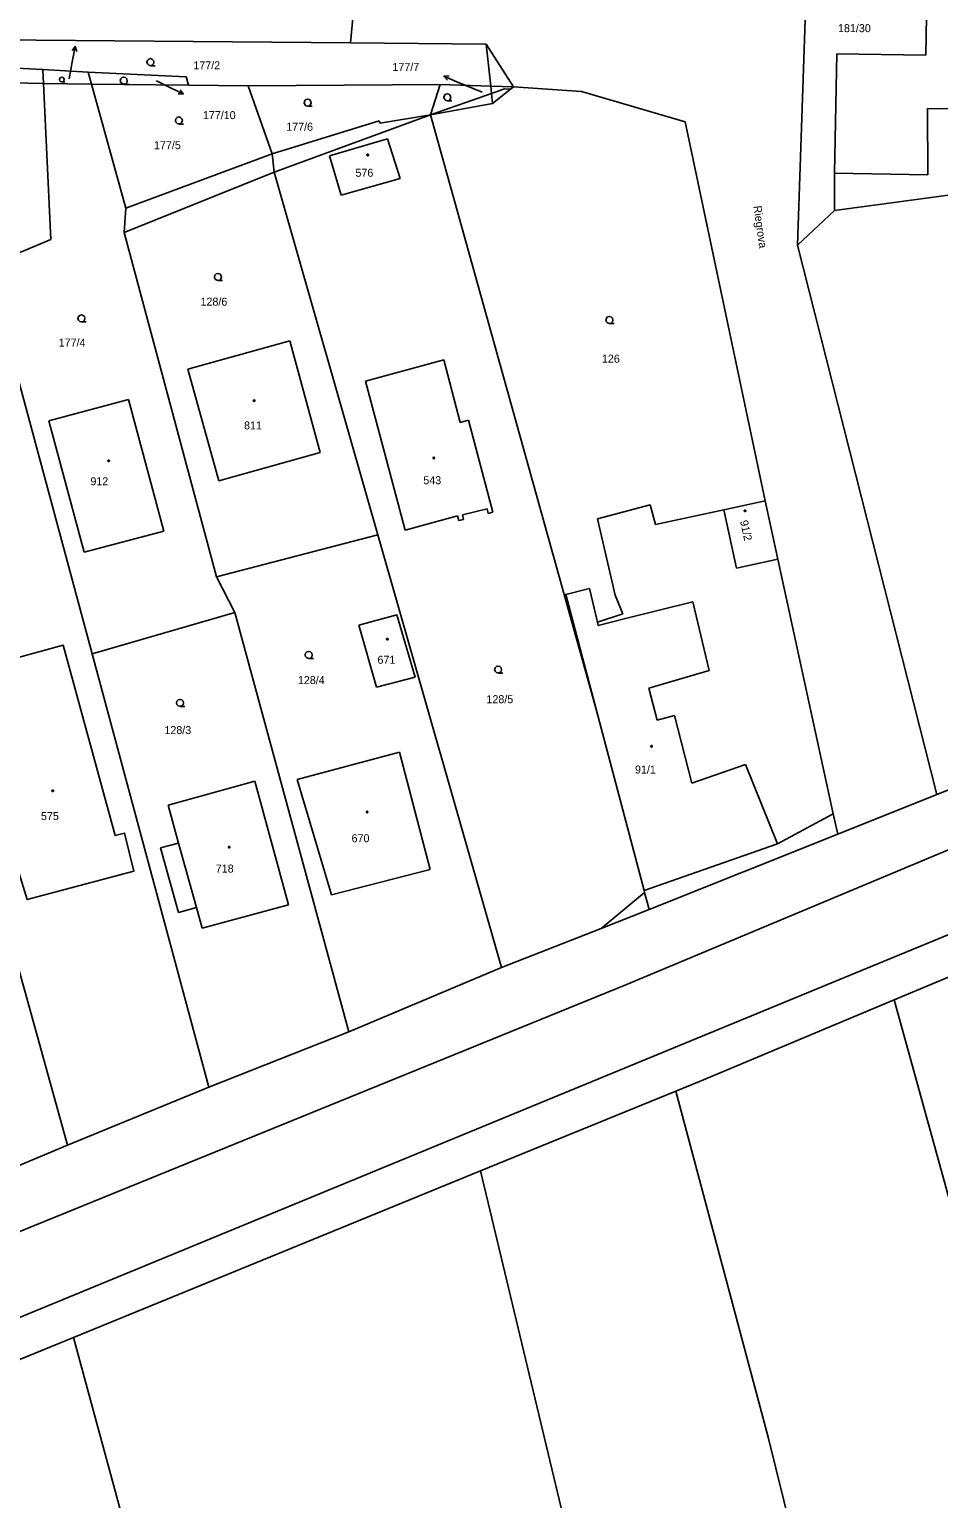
# Model space of a CAD drawing. Extents: x -757994 to -755874, y -1047691 to -1046119.
# Drawn here: x -756280.1 to -756183.5, y -1046741.5 to -1046585.4 of the extents above; entities that cross this region are included whole.
import ezdxf

# ---------------------------------------------------------------- set-up
doc = ezdxf.new("R2010")
doc.units = 0
doc.layers.add('katastrální mapa', color=7, linetype='Continuous')

msp = doc.modelspace()

# ---------------------------------------------------------------- linework, layer by layer
at = {"layer": 'katastrální mapa'}
for p, q in [((-756184.77, -1046581.39), (-756184.91, -1046588.16)), ((-756245.59, -1046582.7), (-756246, -1046586.87)), ((-756197.7, -1046584.41), (-756198.54, -1046608.36)), ((-756246, -1046586.87), (-756293.36, -1046586.44)), ((-756231.57, -1046587), (-756246, -1046586.87)), ((-756275.21, -1046587.24), (-756275.49, -1046588.71)), ((-756228.67, -1046591.53), (-756231.57, -1046587)), ((-756231.1, -1046591.45), (-756231.57, -1046587)), ((-756194.33, -1046588.02), (-756194.61, -1046600.7)), ((-756184.91, -1046588.16), (-756194.33, -1046588.02)), ((-756292.75, -1046588.97), (-756278.67, -1046589.7)), ((-756278.6, -1046591.16), (-756278.67, -1046589.7)), ((-756278.67, -1046589.7), (-756273.85, -1046589.96)), ((-756275.87, -1046590.68), (-756275.49, -1046588.71)), ((-756273.85, -1046589.96), (-756273.49, -1046591.25)), ((-756278.6, -1046591.16), (-756292.3, -1046590.87)), ((-756277.82, -1046607.75), (-756278.6, -1046591.16)), ((-756278.6, -1046591.16), (-756273.49, -1046591.25)), ((-756273.49, -1046591.25), (-756269.84, -1046604.41)), ((-756273.49, -1046591.25), (-756263.18, -1046591.35)), ((-756266.57, -1046590.9), (-756265.09, -1046591.62)), ((-756263.18, -1046591.35), (-756256.84, -1046591.41)), ((-756256.84, -1046591.41), (-756236.47, -1046591.28)), ((-756256.84, -1046591.41), (-756254.32, -1046598.66)), ((-756236.47, -1046591.28), (-756237.5, -1046594.5)), ((-756236.47, -1046591.28), (-756231.1, -1046591.45)), ((-756236.07, -1046590.41), (-756234.68, -1046590.98)), ((-756232.01, -1046592.08), (-756234.68, -1046590.98)), ((-756231.1, -1046591.45), (-756228.67, -1046591.53)), ((-756231.01, -1046592.22), (-756231.1, -1046591.45)), ((-756228.67, -1046591.53), (-756228.98, -1046591.78)), ((-756221.46, -1046592.04), (-756228.67, -1046591.53)), ((-756263.74, -1046592.28), (-756265.09, -1046591.62)), ((-756237.5, -1046594.5), (-756231.01, -1046592.22)), ((-756231.01, -1046592.22), (-756229.64, -1046591.74)), ((-756230.9, -1046593.3), (-756231.01, -1046592.22)), ((-756228.98, -1046591.78), (-756230.9, -1046593.3)), ((-756229.64, -1046591.74), (-756228.98, -1046591.78)), ((-756210.44, -1046595.24), (-756221.46, -1046592.04)), ((-756237.5, -1046594.5), (-756254.1, -1046600.6)), ((-756242.84, -1046595.37), (-756237.5, -1046594.5)), ((-756230.9, -1046593.3), (-756237.5, -1046594.5)), ((-756237.5, -1046594.5), (-756223.29, -1046645.47)), ((-756184.67, -1046600.87), (-756184.71, -1046593.82)), ((-756184.71, -1046593.82), (-756154.21, -1046594.17)), ((-756254.32, -1046598.66), (-756242.94, -1046595.13)), ((-756242.94, -1046595.13), (-756242.84, -1046595.37)), ((-756201.96, -1046635.51), (-756210.44, -1046595.24)), ((-756248.2, -1046598.87), (-756242.04, -1046597.06)), ((-756242.04, -1046597.06), (-756240.72, -1046601.27)), ((-756269.84, -1046604.41), (-756254.32, -1046598.66)), ((-756254.32, -1046598.66), (-756254.1, -1046600.6)), ((-756246.99, -1046603.03), (-756248.2, -1046598.87)), ((-755984.53, -1046599.97), (-756303.8, -1046731.6)), ((-756254.1, -1046600.6), (-756270.03, -1046607.01)), ((-756254.1, -1046600.6), (-756243.09, -1046639.11)), ((-756194.61, -1046600.7), (-756194.59, -1046604.68)), ((-756194.61, -1046600.7), (-756184.67, -1046600.87)), ((-756240.72, -1046601.27), (-756246.99, -1046603.03)), ((-756194.59, -1046604.68), (-756181.7, -1046602.92)), ((-756269.84, -1046604.41), (-756270.03, -1046607.01)), ((-756194.59, -1046604.68), (-756198.54, -1046608.36)), ((-756270.03, -1046607.01), (-756260.2, -1046643.58)), ((-756284.52, -1046610.55), (-756277.82, -1046607.75)), ((-756183.74, -1046666.69), (-756198.54, -1046608.36)), ((-756284.52, -1046610.55), (-756273.42, -1046651.77)), ((-756252.42, -1046618.52), (-756263.25, -1046621.51)), ((-756249.2, -1046630.38), (-756252.42, -1046618.52)), ((-756244.41, -1046622.8), (-756236.06, -1046620.52)), ((-756236.06, -1046620.52), (-756234.33, -1046627.17)), ((-756263.25, -1046621.51), (-756259.98, -1046633.37)), ((-756240.17, -1046638.63), (-756244.41, -1046622.8)), ((-756269.57, -1046624.73), (-756278.01, -1046627)), ((-756265.81, -1046638.72), (-756269.57, -1046624.73)), ((-756278.01, -1046627), (-756274.25, -1046640.96)), ((-756234.33, -1046627.17), (-756233.46, -1046626.95)), ((-756233.46, -1046626.95), (-756230.87, -1046636.72)), ((-756259.98, -1046633.37), (-756249.2, -1046630.38)), ((-756183.74, -1046666.69), (-756104.52, -1046635.21)), ((-756231.49, -1046636.34), (-756234.1, -1046636.99)), ((-756231.38, -1046636.84), (-756231.49, -1046636.34)), ((-756230.87, -1046636.72), (-756231.38, -1046636.84)), ((-756214.17, -1046635.92), (-756219.77, -1046637.41)), ((-756213.61, -1046638.02), (-756214.17, -1046635.92)), ((-756206.36, -1046636.46), (-756213.61, -1046638.02)), ((-756201.96, -1046635.51), (-756206.36, -1046636.46)), ((-756206.36, -1046636.46), (-756205.01, -1046642.66)), ((-756200.61, -1046641.7), (-756201.96, -1046635.51)), ((-756234.62, -1046637.11), (-756240.17, -1046638.63)), ((-756234.48, -1046637.61), (-756234.62, -1046637.11)), ((-756233.98, -1046637.49), (-756234.48, -1046637.61)), ((-756234.1, -1046636.99), (-756233.98, -1046637.49)), ((-756219.77, -1046637.41), (-756217.88, -1046645.54)), ((-756274.25, -1046640.96), (-756265.81, -1046638.72)), ((-756260.2, -1046643.58), (-756243.09, -1046639.11)), ((-756243.09, -1046639.11), (-756229.95, -1046685.08)), ((-756205.01, -1046642.66), (-756200.61, -1046641.7)), ((-756194.72, -1046668.75), (-756200.61, -1046641.7)), ((-756258.25, -1046647.35), (-756260.2, -1046643.58)), ((-756223.12, -1046645.44), (-756223.29, -1046645.47)), ((-756219.86, -1046657.76), (-756223.29, -1046645.47)), ((-756220.61, -1046644.82), (-756223.12, -1046645.44)), ((-756223.12, -1046645.44), (-756219.86, -1046657.76)), ((-756219.76, -1046648.39), (-756220.61, -1046644.82)), ((-756217.88, -1046645.54), (-756217.08, -1046647.49)), ((-756216.93, -1046648.04), (-756209.62, -1046646.22)), ((-756209.62, -1046646.22), (-756207.89, -1046653.53)), ((-756258.25, -1046647.35), (-756273.42, -1046651.77)), ((-756246.17, -1046691.91), (-756258.25, -1046647.35)), ((-756245.11, -1046648.7), (-756241.08, -1046647.61)), ((-756241.08, -1046647.61), (-756239.13, -1046654.22)), ((-756217.08, -1046647.49), (-756219.76, -1046648.39)), ((-756243.23, -1046655.3), (-756245.11, -1046648.7)), ((-756219.76, -1046648.39), (-756219.68, -1046648.73)), ((-756219.68, -1046648.73), (-756216.93, -1046648.04)), ((-756273.42, -1046651.77), (-756261.04, -1046697.77)), ((-756207.89, -1046653.53), (-756214.31, -1046655.39)), ((-756239.13, -1046654.22), (-756243.23, -1046655.3)), ((-756214.31, -1046655.39), (-756213.42, -1046658.8)), ((-756214.82, -1046676.9), (-756219.86, -1046657.76)), ((-756213.42, -1046658.8), (-756211.57, -1046658.32)), ((-756211.57, -1046658.32), (-756209.73, -1046665.48)), ((-756251.65, -1046665.12), (-756240.79, -1046662.21)), ((-756240.79, -1046662.21), (-756237.53, -1046674.67)), ((-756209.73, -1046665.48), (-756204.06, -1046663.5)), ((-756204.06, -1046663.5), (-756200.63, -1046671.93)), ((-756256.15, -1046665.29), (-756265.35, -1046667.83)), ((-756252.58, -1046678.42), (-756256.15, -1046665.29)), ((-756248.02, -1046677.35), (-756251.65, -1046665.12)), ((-756265.35, -1046667.83), (-756264.24, -1046671.85)), ((-756216.75, -1046686.91), (-756169.19, -1046667.01)), ((-756194.23, -1046670.9), (-756183.74, -1046666.69)), ((-756194.72, -1046668.75), (-756200.63, -1046671.93)), ((-756194.23, -1046670.9), (-756194.72, -1046668.75)), ((-756214.29, -1046678.92), (-756194.23, -1046670.9)), ((-756285.05, -1046671.44), (-756276.05, -1046703.93)), ((-756264.24, -1046671.85), (-756266.15, -1046672.38)), ((-756266.15, -1046672.38), (-756264.26, -1046679.24)), ((-756262.32, -1046678.7), (-756264.24, -1046671.85)), ((-756200.63, -1046671.93), (-756214.82, -1046676.9)), ((-756237.53, -1046674.67), (-756248.02, -1046677.35)), ((-756214.76, -1046677.12), (-756219.37, -1046680.92)), ((-756214.82, -1046676.9), (-756214.76, -1046677.12)), ((-756214.76, -1046677.12), (-756214.29, -1046678.92)), ((-756264.26, -1046679.24), (-756262.32, -1046678.7)), ((-756262.32, -1046678.7), (-756261.72, -1046680.88)), ((-756261.72, -1046680.88), (-756252.58, -1046678.42)), ((-756219.37, -1046680.92), (-756214.29, -1046678.92)), ((-756229.95, -1046685.08), (-756219.37, -1046680.92)), ((-756246.17, -1046691.91), (-756229.95, -1046685.08)), ((-756188.26, -1046688.52), (-756179.61, -1046684.89)), ((-756307.54, -1046723.85), (-756216.75, -1046686.91)), ((-756208.92, -1046697.19), (-756188.26, -1046688.52)), ((-756188.26, -1046688.52), (-756166.99, -1046765.66)), ((-756261.04, -1046697.77), (-756246.17, -1046691.91)), ((-756211.43, -1046698.21), (-756208.92, -1046697.19)), ((-756276.05, -1046703.93), (-756261.04, -1046697.77)), ((-756232.17, -1046706.69), (-756211.43, -1046698.21)), ((-756211.43, -1046698.21), (-756201.64, -1046734.96)), ((-756291.03, -1046710.25), (-756276.05, -1046703.93)), ((-756275.39, -1046724.36), (-756232.17, -1046706.69)), ((-756232.17, -1046706.69), (-756210.17, -1046798.54)), ((-756310.88, -1046738.86), (-756275.39, -1046724.36)), ((-756275.39, -1046724.36), (-756254.94, -1046799.93)), ((-756201.64, -1046734.96), (-756197.22, -1046752.78))]:
    msp.add_line(p, q, dxfattribs=at)
for points in [[(-756275.55, -1046587.68), (-756275.21, -1046587.24), (-756275.06, -1046587.77)], [(-756273.85, -1046589.96), (-756263.42, -1046590.47), (-756263.18, -1046591.35)], [(-756267.22, -1046589.27), (-756267.41, -1046589.22), (-756267.54, -1046589.09), (-756267.6, -1046588.9), (-756267.54, -1046588.72), (-756267.41, -1046588.58), (-756267.23, -1046588.53), (-756267.04, -1046588.58), (-756266.91, -1046588.72), (-756266.85, -1046588.91), (-756266.91, -1046589.1), (-756267.04, -1046589.23), (-756267.23, -1046589.28), (-756266.73, -1046589.28)], [(-756276.63, -1046591), (-756276.76, -1046590.97), (-756276.85, -1046590.88), (-756276.88, -1046590.75), (-756276.85, -1046590.63), (-756276.76, -1046590.54), (-756276.63, -1046590.5), (-756276.51, -1046590.54), (-756276.42, -1046590.63), (-756276.39, -1046590.76), (-756276.42, -1046590.88), (-756276.51, -1046590.97), (-756276.64, -1046591.01), (-756276.3, -1046591.01)], [(-756270.05, -1046591.24), (-756270.24, -1046591.19), (-756270.38, -1046591.05), (-756270.43, -1046590.87), (-756270.38, -1046590.69), (-756270.24, -1046590.55), (-756270.06, -1046590.5), (-756269.87, -1046590.55), (-756269.74, -1046590.69), (-756269.69, -1046590.88), (-756269.74, -1046591.07), (-756269.87, -1046591.2), (-756270.06, -1046591.25), (-756269.56, -1046591.25)], [(-756235.7, -1046590.83), (-756236.07, -1046590.41), (-756235.51, -1046590.37)], [(-756264.08, -1046591.83), (-756263.74, -1046592.28), (-756264.3, -1046592.28)], [(-756250.53, -1046593.58), (-756250.72, -1046593.53), (-756250.85, -1046593.4), (-756250.91, -1046593.21), (-756250.85, -1046593.02), (-756250.72, -1046592.89), (-756250.54, -1046592.84), (-756250.35, -1046592.89), (-756250.22, -1046593.02), (-756250.17, -1046593.22), (-756250.22, -1046593.41), (-756250.35, -1046593.54), (-756250.54, -1046593.59), (-756250.04, -1046593.59)], [(-756235.7, -1046593.01), (-756235.89, -1046592.96), (-756236.02, -1046592.83), (-756236.08, -1046592.64), (-756236.02, -1046592.46), (-756235.89, -1046592.32), (-756235.71, -1046592.27), (-756235.52, -1046592.32), (-756235.39, -1046592.46), (-756235.34, -1046592.65), (-756235.39, -1046592.84), (-756235.52, -1046592.97), (-756235.71, -1046593.02), (-756235.21, -1046593.02)], [(-756264.2, -1046595.47), (-756264.39, -1046595.42), (-756264.52, -1046595.28), (-756264.58, -1046595.1), (-756264.52, -1046594.92), (-756264.39, -1046594.78), (-756264.21, -1046594.73), (-756264.02, -1046594.78), (-756263.89, -1046594.92), (-756263.84, -1046595.11), (-756263.89, -1046595.29), (-756264.02, -1046595.43), (-756264.21, -1046595.48), (-756263.71, -1046595.48)], [(-756260.05, -1046612.09), (-756260.24, -1046612.04), (-756260.38, -1046611.91), (-756260.43, -1046611.72), (-756260.38, -1046611.53), (-756260.24, -1046611.4), (-756260.06, -1046611.35), (-756259.87, -1046611.4), (-756259.74, -1046611.53), (-756259.69, -1046611.73), (-756259.74, -1046611.92), (-756259.87, -1046612.05), (-756260.06, -1046612.1), (-756259.56, -1046612.1)], [(-756274.54, -1046616.49), (-756274.73, -1046616.44), (-756274.86, -1046616.3), (-756274.92, -1046616.12), (-756274.86, -1046615.94), (-756274.73, -1046615.8), (-756274.55, -1046615.75), (-756274.36, -1046615.8), (-756274.23, -1046615.94), (-756274.18, -1046616.12), (-756274.23, -1046616.32), (-756274.36, -1046616.45), (-756274.55, -1046616.5), (-756274.05, -1046616.5)], [(-756218.49, -1046616.66), (-756218.68, -1046616.61), (-756218.82, -1046616.48), (-756218.86, -1046616.29), (-756218.82, -1046616.11), (-756218.68, -1046615.97), (-756218.49, -1046615.92), (-756218.31, -1046615.97), (-756218.18, -1046616.11), (-756218.12, -1046616.3), (-756218.18, -1046616.49), (-756218.31, -1046616.62), (-756218.5, -1046616.67), (-756218, -1046616.67)], [(-756284.28, -1046669.1), (-756287.04, -1046658.54), (-756285.71, -1046658.19), (-756286.88, -1046653.67), (-756276.48, -1046650.85), (-756270.99, -1046671.04), (-756269.97, -1046670.79), (-756268.99, -1046674.85)], [(-756250.42, -1046652.24), (-756250.61, -1046652.19), (-756250.75, -1046652.05), (-756250.8, -1046651.87), (-756250.75, -1046651.69), (-756250.61, -1046651.55), (-756250.43, -1046651.5), (-756250.24, -1046651.55), (-756250.1, -1046651.69), (-756250.06, -1046651.88), (-756250.1, -1046652.07), (-756250.24, -1046652.2), (-756250.43, -1046652.25), (-756249.93, -1046652.25)], [(-756230.3, -1046653.79), (-756230.49, -1046653.74), (-756230.62, -1046653.61), (-756230.68, -1046653.42), (-756230.62, -1046653.24), (-756230.49, -1046653.1), (-756230.31, -1046653.05), (-756230.12, -1046653.1), (-756229.99, -1046653.24), (-756229.94, -1046653.43), (-756229.99, -1046653.62), (-756230.12, -1046653.75), (-756230.31, -1046653.8), (-756229.81, -1046653.8)], [(-756264.08, -1046657.33), (-756264.27, -1046657.28), (-756264.41, -1046657.15), (-756264.46, -1046656.96), (-756264.41, -1046656.77), (-756264.27, -1046656.64), (-756264.09, -1046656.59), (-756263.9, -1046656.64), (-756263.76, -1046656.77), (-756263.72, -1046656.97), (-756263.76, -1046657.16), (-756263.9, -1046657.29), (-756264.09, -1046657.34), (-756263.59, -1046657.34)], [(-756268.99, -1046674.85), (-756280.33, -1046677.86), (-756281.44, -1046674.16), (-756282.4, -1046670.75)]]:
    msp.add_lwpolyline(points, dxfattribs=at)
for points in [[(-756244.16, -1046598.68), (-756244.11, -1046598.69), (-756244.09, -1046598.73), (-756244.08, -1046598.76), (-756244.09, -1046598.8), (-756244.12, -1046598.84), (-756244.16, -1046598.85), (-756244.21, -1046598.83), (-756244.24, -1046598.8), (-756244.25, -1046598.76), (-756244.24, -1046598.72), (-756244.2, -1046598.68)], [(-756256.23, -1046624.77), (-756256.18, -1046624.78), (-756256.16, -1046624.83), (-756256.15, -1046624.86), (-756256.16, -1046624.91), (-756256.2, -1046624.94), (-756256.23, -1046624.95), (-756256.27, -1046624.93), (-756256.3, -1046624.9), (-756256.32, -1046624.86), (-756256.3, -1046624.82), (-756256.26, -1046624.78)], [(-756271.66, -1046631.17), (-756271.61, -1046631.18), (-756271.59, -1046631.22), (-756271.58, -1046631.25), (-756271.59, -1046631.29), (-756271.62, -1046631.33), (-756271.66, -1046631.34), (-756271.71, -1046631.32), (-756271.74, -1046631.29), (-756271.75, -1046631.25), (-756271.74, -1046631.21), (-756271.7, -1046631.17)], [(-756237.13, -1046630.88), (-756237.08, -1046630.89), (-756237.05, -1046630.93), (-756237.04, -1046630.96), (-756237.05, -1046631), (-756237.1, -1046631.04), (-756237.13, -1046631.04), (-756237.18, -1046631.03), (-756237.21, -1046631), (-756237.22, -1046630.96), (-756237.21, -1046630.92), (-756237.17, -1046630.88)], [(-756204.1, -1046636.48), (-756204.05, -1046636.49), (-756204.02, -1046636.53), (-756204.01, -1046636.56), (-756204.02, -1046636.61), (-756204.07, -1046636.64), (-756204.1, -1046636.65), (-756204.15, -1046636.63), (-756204.18, -1046636.6), (-756204.19, -1046636.56), (-756204.18, -1046636.52), (-756204.14, -1046636.48)], [(-756242.08, -1046650.12), (-756242.03, -1046650.12), (-756242, -1046650.17), (-756241.99, -1046650.2), (-756242, -1046650.24), (-756242.04, -1046650.28), (-756242.08, -1046650.28), (-756242.12, -1046650.27), (-756242.16, -1046650.24), (-756242.17, -1046650.2), (-756242.16, -1046650.16), (-756242.11, -1046650.12)], [(-756214.02, -1046661.5), (-756213.97, -1046661.51), (-756213.95, -1046661.56), (-756213.94, -1046661.59), (-756213.95, -1046661.64), (-756213.99, -1046661.67), (-756214.02, -1046661.68), (-756214.07, -1046661.66), (-756214.1, -1046661.63), (-756214.1, -1046661.59), (-756214.1, -1046661.54), (-756214.05, -1046661.51)], [(-756277.6, -1046666.22), (-756277.55, -1046666.23), (-756277.52, -1046666.27), (-756277.51, -1046666.3), (-756277.52, -1046666.35), (-756277.57, -1046666.38), (-756277.6, -1046666.39), (-756277.65, -1046666.37), (-756277.68, -1046666.34), (-756277.69, -1046666.3), (-756277.68, -1046666.26), (-756277.64, -1046666.22)], [(-756244.22, -1046668.48), (-756244.17, -1046668.49), (-756244.15, -1046668.53), (-756244.14, -1046668.56), (-756244.15, -1046668.61), (-756244.19, -1046668.64), (-756244.22, -1046668.65), (-756244.26, -1046668.63), (-756244.29, -1046668.6), (-756244.3, -1046668.56), (-756244.29, -1046668.52), (-756244.25, -1046668.48)], [(-756258.87, -1046672.22), (-756258.82, -1046672.23), (-756258.79, -1046672.27), (-756258.78, -1046672.3), (-756258.79, -1046672.35), (-756258.84, -1046672.38), (-756258.87, -1046672.39), (-756258.92, -1046672.37), (-756258.95, -1046672.34), (-756258.96, -1046672.3), (-756258.95, -1046672.26), (-756258.91, -1046672.22)]]:
    msp.add_lwpolyline(points, close=True, dxfattribs=at)

# ---------------------------------------------------------------- texts
for s, height, p in [('181/30', 0.85, (-756194.22, -1046585.72)), ('177/2', 0.85, (-756262.67, -1046589.67)), ('177/7', 0.85, (-756241.53, -1046589.84)), ('177/9', 0.05, (-756275.96, -1046590.68)), ('177/10', 0.05, (-756266.67, -1046590.9)), ('177/7', 0.05, (-756232.1, -1046592.08)), ('177/10', 0.85, (-756261.66, -1046594.96)), ('177/6', 0.85, (-756252.81, -1046596.19)), ('177/5', 0.85, (-756266.85, -1046598.15)), ('576', 0.85, (-756245.46, -1046601.08)), ('128/6', 0.85, (-756261.91, -1046614.77)), ('177/4', 0.85, (-756276.97, -1046619.12)), ('126', 0.85, (-756219.29, -1046620.83)), ('811', 0.85, (-756257.29, -1046627.92)), ('912', 0.85, (-756273.6, -1046633.85)), ('543', 0.85, (-756238.25, -1046633.74)), ('671', 0.85, (-756243.12, -1046652.81)), ('128/4', 0.85, (-756251.57, -1046654.97)), ('128/5', 0.85, (-756231.55, -1046657)), ('128/3', 0.85, (-756265.74, -1046660.28)), ('91/1', 0.85, (-756215.78, -1046664.47)), ('575', 0.85, (-756278.85, -1046669.41)), ('670', 0.85, (-756245.87, -1046671.77)), ('718', 0.85, (-756260.29, -1046674.99))]:
    msp.add_text(s, height=height, dxfattribs=at).set_placement(p)
for s, rotation, p in [('Riegrova', 278.0564, (-756203.21, -1046604.21)), ('91/2', 282.2963, (-756204.63, -1046637.66))]:
    msp.add_text(s, height=0.85, rotation=rotation, dxfattribs=at).set_placement(p)

doc.saveas('drawing.dxf')
